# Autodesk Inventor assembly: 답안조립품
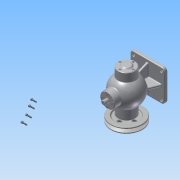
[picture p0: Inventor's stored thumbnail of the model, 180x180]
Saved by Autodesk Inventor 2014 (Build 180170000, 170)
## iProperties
Created: 2017-01
Part Number: 답안조립품
Document SubType Name: Assembly
Designer: ksu
Author: ksu
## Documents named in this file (19)
- C:\Users\ksu\Desktop\470118V1011\470118V1011\답안조립품.iam
- C:\Users\ksu\Desktop\470118V1011\470118V1011\V-벨트풀리.ipt
- C:\Users\ksu\Desktop\470118V1011\470118V1011\너트 M8.ipt
- C:\Users\ksu\Desktop\470118V1011\470118V1011\뒤커버.ipt
- C:\Users\ksu\Desktop\470118V1011\470118V1011\멈춤링- 15 x 1.ipt
- C:\Users\ksu\Desktop\470118V1011\470118V1011\멈춤링- 35x1.6.ipt
- KS B 1336 - 35x1.6.ipt
- C:\Users\ksu\Desktop\470118V1011\470118V1011\베어링- 6202.ipt
- KS B 2023 - 6202 - 15 x 35 x 11 - 7.8.ipt
- C:\Users\ksu\Desktop\470118V1011\470118V1011\볼트 M4 x 12.ipt
- C:\Users\ksu\Desktop\470118V1011\470118V1011\볼트 M4 x 16.ipt
- C:\Users\ksu\Desktop\470118V1011\470118V1011\부시.ipt
- C:\Users\ksu\Desktop\470118V1011\470118V1011\상부커버.ipt
- C:\Users\ksu\Desktop\470118V1011\470118V1011\슬라이드.ipt
- C:\Users\ksu\Desktop\470118V1011\470118V1011\앞커버.ipt
- C:\Users\ksu\Desktop\470118V1011\470118V1011\오일실 15 30 7.ipt
- C:\Users\ksu\Desktop\470118V1011\470118V1011\키 4 x 4 x 12.ipt
- C:\Users\ksu\Desktop\470118V1011\470118V1011\편심축.ipt
- C:\Users\ksu\Desktop\본체.ipt
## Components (16 placed, 5 different names)
1. V-벨트풀리:1 — Mate:3, Mate:5, Mate:6, Mate:8
2. KS B 1336 - 35x1.6:1 — Mate:18, Mate:19
3. KS B 2023 - 6202 - 15 x 35 x 11 - 7.8:1 — Mate:16, Mate:17, Mate:18, Mate:19, Mate:20, Mate:26
4. KS B 1021 - 에 따름 ISO 1207 - 미터 A  M 4 x 12:1 — Mate:33, Mate:39
5. ISO 4762 M4 x 16:1 — Mate:41, Flush:2
6. KS B 2023 - 6202 - 15 x 35 x 11 - 7.8:2 — Mate:10, Mate:11, Mate:13
7. KS B 1021 - 에 따름 ISO 1207 - 미터 A  M 4 x 12:2 — Mate:36, Mate:40
8. KS B 1021 - 에 따름 ISO 1207 - 미터 A  M 4 x 12:3 — Mate:35, Mate:37
9. KS B 1021 - 에 따름 ISO 1207 - 미터 A  M 4 x 12:4 — Mate:34, Mate:38
10. ISO 4762 M4 x 16:2 — Mate:42, Flush:4
11. ISO 4762 M4 x 16:3 — Mate:43, Flush:3
12. ISO 4762 M4 x 16:4 — Mate:44, Mate:45
13. ISO 4762 M4 x 16:5
14. ISO 4762 M4 x 16:6
15. ISO 4762 M4 x 16:7
16. ISO 4762 M4 x 16:8
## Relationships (29: Mate 26, Flush 3)
- Mate:3: V-벨트풀리:1
- Mate:5: V-벨트풀리:1
- Mate:6: V-벨트풀리:1
- Mate:8: V-벨트풀리:1
- Mate:10: KS B 2023 - 6202 - 15 x 35 x 11 - 7.8:2
- Mate:11: KS B 2023 - 6202 - 15 x 35 x 11 - 7.8:2
- Mate:13: KS B 2023 - 6202 - 15 x 35 x 11 - 7.8:2
- Mate:16: KS B 2023 - 6202 - 15 x 35 x 11 - 7.8:1
- Mate:17: KS B 2023 - 6202 - 15 x 35 x 11 - 7.8:1
- Mate:18: KS B 1336 - 35x1.6:1 ↔ KS B 2023 - 6202 - 15 x 35 x 11 - 7.8:1
- Mate:19: KS B 1336 - 35x1.6:1 ↔ KS B 2023 - 6202 - 15 x 35 x 11 - 7.8:1
- Mate:20: KS B 2023 - 6202 - 15 x 35 x 11 - 7.8:1
- Mate:26: KS B 2023 - 6202 - 15 x 35 x 11 - 7.8:1
- Mate:33: KS B 1021 - 에 따름 ISO 1207 - 미터 A  M 4 x 12:1
- Mate:34: KS B 1021 - 에 따름 ISO 1207 - 미터 A  M 4 x 12:4
- Mate:35: KS B 1021 - 에 따름 ISO 1207 - 미터 A  M 4 x 12:3
- Mate:36: KS B 1021 - 에 따름 ISO 1207 - 미터 A  M 4 x 12:2
- Mate:37: KS B 1021 - 에 따름 ISO 1207 - 미터 A  M 4 x 12:3
- Mate:38: KS B 1021 - 에 따름 ISO 1207 - 미터 A  M 4 x 12:4
- Mate:39: KS B 1021 - 에 따름 ISO 1207 - 미터 A  M 4 x 12:1
- Mate:40: KS B 1021 - 에 따름 ISO 1207 - 미터 A  M 4 x 12:2
- Mate:41: ISO 4762 M4 x 16:1
- Mate:42: ISO 4762 M4 x 16:2
- Mate:43: ISO 4762 M4 x 16:3
- Mate:44: ISO 4762 M4 x 16:4
- Flush:2: ISO 4762 M4 x 16:1
- Flush:3: ISO 4762 M4 x 16:3
- Flush:4: ISO 4762 M4 x 16:2
- Mate:45: ISO 4762 M4 x 16:4
